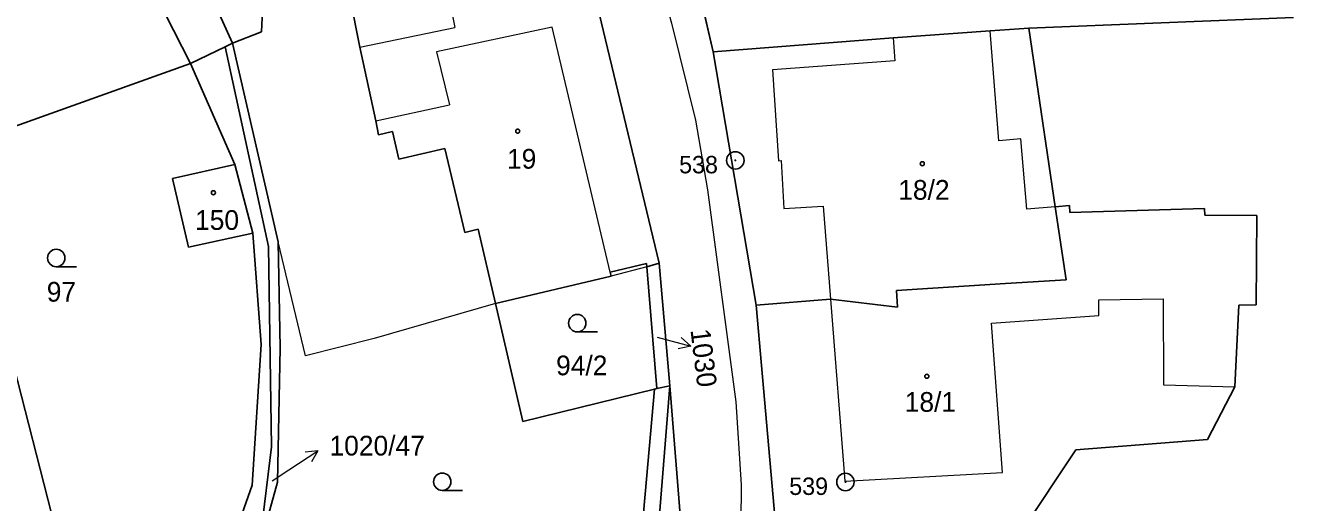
# Model space of a CAD drawing. Extents: x -601131 to -597152, y -1058536 to -1055911.
# Drawn here: x -599472.1 to -599362.8, y -1056976.5 to -1056935.4 of the extents above; entities that cross this region are included whole.
import ezdxf
from ezdxf.enums import TextEntityAlignment as Align

# ---------------------------------------------------------------- set-up
doc = ezdxf.new("R2010")
doc.units = 0
doc.header["$LTSCALE"] = 0.68
for name, color, linetype, lineweight in [('1', 7, 'Continuous', 25), ('13', 7, 'Continuous', 13), ('3', 7, 'Continuous', 25), ('4', 7, 'Continuous', 13), ('5', 7, 'Continuous', 25), ('7', 7, 'Continuous', 13), ('8', 7, 'Continuous', 25)]:
    doc.layers.add(name, color=color, linetype=linetype, lineweight=lineweight)
doc.layers.add('2', color=7, linetype='Continuous')

msp = doc.modelspace()

# ---------------------------------------------------------------- linework, layer by layer
at = {"layer": '1'}
for p, q in [((-599454.23, -1056936.91), (-599463.12, -1056917.08)), ((-599457.86, -1056938.65), (-599467.5, -1056919.74)), ((-599417.45, -1056955.89), (-599425.36, -1056922.97)), ((-599445.29, -1056927), (-599443.26, -1056937.24)), ((-599414.89, -1056928.62), (-599412.79, -1056937.66)), ((-599451.74, -1056935.92), (-599451.45, -1056929.97)), ((-599385.6, -1056935.62), (-599362.77, -1056934.7)), ((-599454.23, -1056936.91), (-599451.74, -1056935.92)), ((-599412.79, -1056937.66), (-599397.28, -1056936.44)), ((-599397.28, -1056936.44), (-599388.93, -1056935.85)), ((-599388.93, -1056935.85), (-599385.6, -1056935.62)), ((-599383.31, -1056951.02), (-599385.6, -1056935.62)), ((-599457.86, -1056938.65), (-599454.87, -1056937.21)), ((-599454.87, -1056937.21), (-599454.23, -1056936.91)), ((-599451.14, -1056954.43), (-599454.87, -1056937.21)), ((-599450.29, -1056954.03), (-599454.23, -1056936.91)), ((-599441.87, -1056943.6), (-599443.26, -1056937.24)), ((-599412.79, -1056937.66), (-599409.1, -1056959.5)), ((-599457.86, -1056938.65), (-599495.55, -1056952.15)), ((-599454.02, -1056947.38), (-599457.86, -1056938.65)), ((-599441.87, -1056943.6), (-599441.65, -1056944.8)), ((-599441.65, -1056944.8), (-599440.43, -1056944.53)), ((-599440.43, -1056944.53), (-599439.9, -1056946.92)), ((-599439.9, -1056946.92), (-599435.93, -1056945.98)), ((-599435.93, -1056945.98), (-599434.22, -1056953.22)), ((-599459.39, -1056948.57), (-599454.02, -1056947.38)), ((-599452.48, -1056953.28), (-599454.02, -1056947.38)), ((-599458.01, -1056954.5), (-599459.39, -1056948.57)), ((-599382.1, -1056950.91), (-599383.31, -1056951.02)), ((-599382.38, -1056957.31), (-599383.31, -1056951.02)), ((-599382.05, -1056951.52), (-599382.1, -1056950.91)), ((-599370.45, -1056951.17), (-599382.05, -1056951.52)), ((-599370.43, -1056951.73), (-599370.45, -1056951.17)), ((-599365.93, -1056951.77), (-599370.43, -1056951.73)), ((-599366, -1056959.46), (-599365.93, -1056951.77)), ((-599434.22, -1056953.22), (-599433.07, -1056952.94)), ((-599433.07, -1056952.94), (-599431.56, -1056959.36)), ((-599452.48, -1056953.28), (-599458.01, -1056954.5)), ((-599451.76, -1056962.88), (-599452.48, -1056953.28)), ((-599450.12, -1056963.18), (-599450.29, -1056954.03)), ((-599450.86, -1056971.71), (-599451.14, -1056954.43)), ((-599421.68, -1056956.65), (-599418.55, -1056955.91)), ((-599418.55, -1056955.91), (-599418.53, -1056956.18)), ((-599418.53, -1056956.18), (-599417.45, -1056955.89)), ((-599417.67, -1056966.69), (-599418.53, -1056956.18)), ((-599417.45, -1056955.89), (-599416.53, -1056966.46)), ((-599431.56, -1056959.36), (-599421.6, -1056957)), ((-599421.6, -1056957), (-599421.68, -1056956.65)), ((-599387.6, -1056957.62), (-599382.38, -1056957.31)), ((-599396.99, -1056958.22), (-599387.6, -1056957.62)), ((-599396.9, -1056959.67), (-599396.99, -1056958.22)), ((-599431.56, -1056959.36), (-599429.22, -1056969.54)), ((-599409.1, -1056959.5), (-599402.68, -1056958.98)), ((-599409.1, -1056959.5), (-599407.35, -1056979.16)), ((-599402.68, -1056958.98), (-599396.9, -1056959.67)), ((-599367.83, -1056966.55), (-599367.48, -1056959.51)), ((-599367.48, -1056959.51), (-599366, -1056959.46)), ((-599452.54, -1056975.02), (-599451.76, -1056962.88)), ((-599450.12, -1056963.18), (-599450.36, -1056974.77)), ((-599469.83, -1056977.46), (-599473.08, -1056964.77)), ((-599429.22, -1056969.54), (-599417.86, -1056966.74)), ((-599418.06, -1056985.36), (-599416.53, -1056966.46)), ((-599417.86, -1056966.74), (-599417.67, -1056966.69)), ((-599416.53, -1056966.46), (-599417.67, -1056966.69)), ((-599414.84, -1056987.77), (-599416.53, -1056966.46)), ((-599367.83, -1056966.55), (-599370.18, -1056971.09)), ((-599381.53, -1056971.98), (-599370.18, -1056971.09)), ((-599451.94, -1056980.47), (-599450.86, -1056971.71)), ((-599381.53, -1056971.98), (-599387.3, -1056980.59)), ((-599451.94, -1056980.47), (-599450.36, -1056974.77)), ((-599457.28, -1056988.51), (-599452.54, -1056975.02))]:
    msp.add_line(p, q, dxfattribs=at)
msp.add_lwpolyline([(-599417.86, -1056966.74), (-599419.51, -1056985.16), (-599421.08, -1056985.09)], dxfattribs=at)
at = {"layer": '13'}
for points in [[(-599435.97, -1056861.08), (-599434.58, -1056869.5), (-599432.48, -1056879.1), (-599425.21, -1056904.03), (-599421.86, -1056915.62), (-599416.39, -1056935.17), (-599414.31, -1056943.54), (-599413.29, -1056949.55), (-599410.84, -1056967.85), (-599410.4, -1056975), (-599410.48, -1056984.78), (-599411.21, -1056997.76), (-599412.32, -1057011.09), (-599414.73, -1057032.27), (-599417.11, -1057047.5), (-599419.27, -1057067.05)], [(-599416.28, -1057067.22), (-599414.13, -1057047.91), (-599411.76, -1057032.68), (-599409.33, -1057011.38), (-599407.96, -1056995.84), (-599407.36, -1056980.13), (-599407.35, -1056979.16), (-599409.1, -1056959.5), (-599412.79, -1056937.66), (-599414.89, -1056928.62), (-599418.98, -1056914.8), (-599422.34, -1056903.17), (-599429.56, -1056878.4), (-599431.63, -1056868.93), (-599432.99, -1056860.71)]]:
    msp.add_lwpolyline(points, dxfattribs=at)
at = {"layer": '3'}
for p, q in [((-599469.423, -1056956.18), (-599467.673, -1056956.18)), ((-599424.513, -1056961.8), (-599422.763, -1056961.8)), ((-599436.153, -1056975.48), (-599434.403, -1056975.48))]:
    msp.add_line(p, q, dxfattribs=at)
for centre in [(-599469.4229, -1056955.4298), (-599424.5129, -1056961.0498), (-599436.1529, -1056974.7298)]:
    msp.add_circle(centre, 0.75, dxfattribs=at)
at = {"layer": '4'}
for p, q in [((-599436.32, -1056929.28), (-599435.07, -1056935.55)), ((-599443.26, -1056937.24), (-599435.07, -1056935.55)), ((-599426.68, -1056935.53), (-599436.66, -1056937.65)), ((-599421.68, -1056956.65), (-599426.68, -1056935.53)), ((-599397.28, -1056936.44), (-599397.14, -1056938.43)), ((-599388.18, -1056945.33), (-599388.93, -1056935.85)), ((-599436.66, -1056937.65), (-599435.53, -1056942.23)), ((-599397.14, -1056938.43), (-599407.69, -1056939.19)), ((-599407.69, -1056939.19), (-599407.17, -1056947.04)), ((-599441.87, -1056943.6), (-599435.53, -1056942.23)), ((-599386.29, -1056945.16), (-599388.18, -1056945.33)), ((-599385.76, -1056951.23), (-599386.29, -1056945.16)), ((-599407.17, -1056947.04), (-599406.94, -1056947.03)), ((-599406.94, -1056947.03), (-599406.7, -1056951.15)), ((-599406.7, -1056951.15), (-599403.31, -1056950.95)), ((-599403.31, -1056950.95), (-599402.68, -1056958.98)), ((-599383.31, -1056951.02), (-599385.76, -1056951.23)), ((-599447.93, -1056963.86), (-599450.29, -1056954.03)), ((-599418.53, -1056956.18), (-599421.6, -1056957)), ((-599431.56, -1056959.36), (-599442.02, -1056962.38)), ((-599402.68, -1056958.98), (-599401.45, -1056974.69)), ((-599379.57, -1056959.04), (-599374.01, -1056958.96)), ((-599379.55, -1056960.38), (-599379.57, -1056959.04)), ((-599374.01, -1056958.96), (-599373.99, -1056966.36)), ((-599388.8, -1056961.04), (-599379.55, -1056960.38)), ((-599387.86, -1056973.94), (-599388.8, -1056961.04)), ((-599442.02, -1056962.38), (-599447.93, -1056963.86)), ((-599373.99, -1056966.36), (-599367.83, -1056966.55)), ((-599401.45, -1056974.69), (-599387.86, -1056973.94))]:
    msp.add_line(p, q, dxfattribs=at)
at = {"layer": '5'}
for centre in [(-599429.6468, -1056944.4892), (-599394.7768, -1056947.2992), (-599455.8768, -1056949.7992), (-599394.3868, -1056965.6292)]:
    msp.add_circle(centre, 0.175, dxfattribs=at)
at = {"layer": '7'}
for p, q in [((-599414.731, -1056963.027), (-599415.569, -1056962.284)), ((-599446.863, -1056972.056), (-599447.976, -1056972.181))]:
    msp.add_line(p, q, dxfattribs=at)
for points in [[(-599417.63, -1056962.25), (-599414.731, -1056963.027), (-599415.828, -1056963.251)], [(-599450.82, -1056974.64), (-599449.38, -1056973.69), (-599446.863, -1056972.056), (-599447.43, -1056973.021)]]:
    msp.add_lwpolyline(points, dxfattribs=at)
at = {"layer": '8'}
for centre, radius in [((-599410.89, -1056947.0098), 0.75), ((-599410.89, -1056947.0098), 0.03), ((-599401.4, -1056974.7498), 0.75), ((-599401.4, -1056974.7498), 0.03)]:
    msp.add_circle(centre, radius, dxfattribs=at)

# ---------------------------------------------------------------- texts
at = {"layer": '2'}
for s, p in [('19', (-599430.57, -1056947.725)), ('18/2', (-599396.85, -1056950.405)), ('150', (-599457.46, -1056953.005)), ('97', (-599470.24, -1056959.195)), ('94/2', (-599426.34, -1056965.545)), ('18/1', (-599396.29, -1056968.695)), ('1020/47', (-599445.87, -1056972.465))]:
    msp.add_text(s, height=1.7, dxfattribs=at).set_placement(p)
msp.add_text('1030', height=1.7, rotation=277, dxfattribs=at).set_placement((-599414.763, -1056961.636))
at = {"layer": '8'}
for s, p in [('538', (-599412.389, -1056948.127)), ('539', (-599402.899, -1056975.867))]:
    msp.add_text(s, height=1.5, dxfattribs=at).set_placement(p, align=Align.RIGHT)

doc.saveas('drawing.dxf')
